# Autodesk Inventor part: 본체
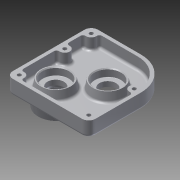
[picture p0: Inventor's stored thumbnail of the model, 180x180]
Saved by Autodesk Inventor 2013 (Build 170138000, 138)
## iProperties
Created: 2015-11
Part Number: 본체
Material: 알루미늄 6061
Document SubType Name: Modeling
Designer: Administrator
Density: 1 g/cm^3
Author: Administrator
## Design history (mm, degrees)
sketch "스케치1"
  geometry: L1 (-44.906, -34.091)-(39.094, -34.091); L2 (47.094, -26.091)-(47.094, 28.909); L3 (7.094, 68.909)-(-44.906, 68.909); L4 (-52.906, 60.909)-(-52.906, -26.091); A1 r 40 centre (7.094, 28.909) between (47.094, 28.909) and (7.094, 68.909); A2 r 8 centre (-44.906, 60.909) between (-44.906, 68.909) and (-52.906, 60.909); A3 r 8 centre (-44.906, -26.091) between (-52.906, -26.091) and (-44.906, -34.091); A4 r 8 centre (39.094, -26.091) between (39.094, -34.091) and (47.094, -26.091); 4 further points
  constraints: 8 end point, 8 point on circle, 8 tangent, 6 point on line, 4 centre point, 2 equal radius, 2 parallel, 1 horizontal, 1 perpendicular
  dimensions: "d0" = 103 distance of point (-52.906, 68.909) point (-52.906, -34.091); "d2" = 100 distance of point (-52.906, -34.091) point (47.094, -34.091); "d3" = 40 radius of A1; "d4" = 8 radius of A2
extrude "돌출1" new body sketch "스케치1" distance "d5" = 18; taper "d6" = 0 deg
sketch "스케치2"
  geometry: L1 (47.094, -26.091)-(47.094, 28.909) reference; L2 (7.094, 68.909)-(-44.906, 68.909) reference; L3 (-52.906, 60.909)-(-52.906, -26.091) reference; L4 (-44.906, -34.091)-(39.094, -34.091) reference; A1 r 40 centre (7.094, 28.909) between (47.094, 28.909) and (7.094, 68.909) reference; A2 r 8 centre (-44.906, 60.909) between (-44.906, 68.909) and (-52.906, 60.909) reference; A3 r 8 centre (-44.906, -26.091) between (-52.906, -26.091) and (-44.906, -34.091) reference; A4 r 8 centre (39.094, -26.091) between (39.094, -34.091) and (47.094, -26.091) reference; 1 further point
feature "쉘1" dims "d9" = 4
sketch "스케치3"
  geometry: L1 (88, 4)-(88, 59) reference; L2 (52, 95)-(0, 95) reference; L3 (-4, 91)-(-4, 4) reference; L4 (0, 0)-(84, 0) reference; L5 (84, -4)-(0, -4) reference; L6 (-8, 4)-(-8, 91) reference; L7 (0, 99)-(52, 99) reference; L8 (92, 59)-(92, 4) reference; L9 (0, 59)-(84, 59); C1 r 6 at (0, 91); C2 r 6 at (0, 4); C3 r 6 at (0, 59); C4 r 6 at (84, 59); C5 r 6 at (84, 4); A1 r 4 centre (0, 91) between (0, 95) and (-4, 91) reference; A2 r 4 centre (0, 4) between (-4, 4) and (0, 0) reference; A3 r 4 centre (84, 4) between (84, 0) and (88, 4) reference; A4 r 36 centre (52, 59) between (88, 59) and (52, 95) reference; A5 r 4 centre (0, 91) between (0, 95) and (-4, 91) reference; A6 r 4 centre (0, 4) between (-4, 4) and (0, 0) reference; A7 r 8 centre (84, 4) between (84, -4) and (92, 4) reference; A8 r 8 centre (0, 4) between (-8, 4) and (0, -4) reference; A9 r 8 centre (0, 91) between (0, 99) and (-8, 91) reference; A10 r 40 centre (52, 59) between (92, 59) and (52, 99) reference; 1 further point
  constraints: 5 centre point, 4 coincident, 2 end point, 1 perpendicular
  dimensions: "d10" = 12 diameter of C1; "d12" = 6 radius of C2; "d14" = 6 radius of C3; "d15" = 84 distance of L9.start L9.end; "d16" = 6 radius of C4; "d17" = 6 radius of C5
extrude "돌출2" join sketch "스케치3" distance "d18" = 14; taper "d19" = 0 deg
fillet "모깎기2" dims "d21" = 3
fillet "모깎기3" dims "d22" = 3
sketch "스케치4"
  geometry: L1 (0, 89)-(43.056, 89) reference; L2 (-9.944, 64.944)-(-9.944, 79.056) reference; L3 (-9.944, 9.944)-(-9.944, 47.056) reference; L4 (66.111, 0)-(0, 0) reference; L5 (76.056, 47.056)-(76.056, 9.944) reference; A1 r 33 centre (43.056, 56) between (74.806, 64.997) and (43.056, 89) reference; A2 r 9 centre (-8.944, 88) between (-9.944, 79.056) and (0, 89) reference; A3 r 9 centre (-8.944, 56) between (-9.944, 47.056) and (-9.944, 64.944) reference; A4 r 9 centre (-8.944, 1) between (0, 0) and (-9.944, 9.944) reference; A5 r 9 centre (75.056, 1) between (76.056, 9.944) and (66.111, 0) reference; A6 r 9 centre (75.056, 56) between (74.806, 64.997) and (76.056, 47.056) reference; 1 further point
sketch "스케치5"
  geometry: L1 (0, 89)-(43.056, 89) reference; L2 (-9.944, 64.944)-(-9.944, 79.056) reference; L3 (-9.944, 9.944)-(-9.944, 47.056) reference; L4 (66.111, 0)-(0, 0) reference; L5 (76.056, 47.056)-(76.056, 9.944) reference; A1 r 33 centre (43.056, 56) between (74.806, 64.997) and (43.056, 89) reference; A2 r 9 centre (-8.944, 88) between (-9.944, 79.056) and (0, 89) reference; A3 r 9 centre (-8.944, 56) between (-9.944, 47.056) and (-9.944, 64.944) reference; A4 r 9 centre (-8.944, 1) between (0, 0) and (-9.944, 9.944) reference; A5 r 9 centre (75.056, 1) between (76.056, 9.944) and (66.111, 0) reference; A6 r 9 centre (75.056, 56) between (74.806, 64.997) and (76.056, 47.056) reference; 1 further point
sketch "스케치6"
  geometry: A1 r 6 centre (-44.906, -26.091) between (-38.943, -26.758) and (-45.573, -20.128) reference; A2 r 6 centre (-44.906, 28.909) between (-45.573, 22.946) and (-45.573, 34.872) reference; A3 r 6 centre (39.094, 28.909) between (38.927, 34.906) and (39.761, 22.946) reference; A4 r 8 centre (-44.906, 60.909) between (-44.906, 68.909) and (-52.906, 60.909) reference; A5 r 8 centre (39.094, -26.091) between (39.094, -34.091) and (47.094, -26.091) reference; 1 further point
hole "구멍1" sketch "스케치6" at (-44.906, 60.909), (-44.906, 28.909), (39.094, 28.909), (39.094, -26.091), (-44.906, -26.091) diameter "d23" = 4.5; stored, may be unused: countersink angle "d27" = 90 deg, drill point angle "d29" = 118 deg; dims "d24" = 6, "d25" = 4, "d26" = 2, "d28" = 8
sketch "스케치7"
  geometry: C1 r 2.25 at (-39.094, -26.091) reference; C2 r 2.25 at (44.906, 28.909) reference; C3 r 2.25 at (44.906, 60.909) reference; C4 r 2.25 at (-39.094, 28.909) reference; C5 r 2.25 at (44.906, -26.091) reference; 1 further point
hole "구멍2" sketch "스케치7" at (-39.094, 28.909), (-39.094, -26.091), (44.906, -26.091), (44.906, 28.909), (44.906, 60.909) diameter "d30" = 4.5; stored, may be unused: countersink angle "d34" = 90 deg, drill point angle "d36" = 118 deg; dims "d31" = 6, "d32" = 8, "d33" = 4.4, "d35" = 17
sketch "스케치8"
  geometry: L1 (-16.944, 88)-(-16.944, 1) reference; L2 (-8.944, -7)-(75.056, -7) reference; L3 (-16.944, 1)-(-16.944, -7); L4 (-9.944, -7)-(-16.944, -7); L5 (-16.944, -7)-(13.056, -7); L6 (13.056, -7)-(13.056, 23); L7 (13.056, 23)-(-16.944, 23); L8 (-16.944, 23)-(-16.944, -7); L9 (-16.944, -7)-(46.056, -7); L10 (46.056, -7)-(46.056, 53); L11 (46.056, 53)-(-16.944, 53); L12 (-16.944, 53)-(-16.944, -7); C1 r 20 at (13.056, 23); C2 r 20 at (46.056, 53); 1 further point
  constraints: 20 end point, 4 parallel, 4 perpendicular, 2 centre point, 2 coincident, 2 horizontal
  dimensions: "d37" = 30 distance of L7.end L6.end; "d38" = 30 distance of L6.end L5.end; "d40" = 20 radius of C1; "d41" = 63 distance of L11.end L10.end; "d42" = 60 distance of L10.end L9.end; "d43" = 20 radius of C2
extrude "돌출3" join sketch "스케치8" distance "d44" = 11; taper "d45" = -10 deg
fillet "모깎기4" dims "d46" = 3
sketch "스케치10"
  geometry: C1 r 18.06 at (0, 0) reference; 1 further point
hole "구멍4" sketch "스케치10" at (0, 0) diameter "d54" = 20; stored, may be unused: countersink angle "d58" = 90 deg, drill point angle "d60" = 118 deg; dims "d55" = 6, "d56" = 32, "d57" = 9, "d59" = 50
chamfer "모따기1" distance "d61" = 1; stored, may be unused: second distance "d62" = 2, angle "d63" = 45 deg
fillet "모깎기5" dims "d64" = 0.3
sketch "스케치11"
  geometry: C1 r 10 at (22.906, -4.091) reference; C2 r 25 at (22.906, -2.936); 1 further point
  constraints: 1 centre point
  dimensions: "d65" = 25 radius of C2
extrude "돌출4" join sketch "스케치11" distance "d66" = 15; taper "d67" = -10 deg
sketch "스케치15"
  geometry: L1 (52.906, -26.091)-(52.906, 60.909) reference; L2 (44.906, 68.909)-(-7.094, 68.909) reference; 2 further points
  constraints: 1 other
  dimensions: "d91" = 40 distance from line of L1 point (12.906, 48.909); "d92" = 20 distance from line of point (12.906, 48.909) L2
feature "엠보싱1" sketch "스케치15" dims "d0" = 103, "d2" = 100, "d3" = 40, "d4" = 8, "d93" = 0.5, "d94" = 0
fillet "모깎기8" dims "d95" = 3
fillet "모깎기9" dims "d96" = 3
sketch "스케치16"
  geometry: C1 r 18.06 at (0, 0) reference; C2 r 16 at (0, 0); 1 further point
  constraints: 1 centre point, 1 coincident
  dimensions: "d97" = 32 diameter of C2
extrude "돌출7" cut sketch "스케치16" distance "d98" = 9; taper "d99" = 0 deg
chamfer "모따기3" distance "d103" = 1; stored, may be unused: second distance "d104" = 2, angle "d105" = 45 deg
fillet "모깎기10" dims "d106" = 0.3
sketch "스케치18"
  geometry: C1 r 12.645 at (0, -1.155) reference; C2 r 14 at (0, -1.155); 1 further point
  constraints: 1 centre point, 1 coincident
  dimensions: "d107" = 28 diameter of C2
extrude "돌출9" cut sketch "스케치18" distance "d108" = 11; taper "d109" = 0 deg
chamfer "모따기4" distance "d110" = 1; stored, may be unused: second distance "d111" = 2, angle "d112" = 45 deg
fillet "모깎기11" dims "d113" = 0.3
sketch "스케치19"
  geometry: C1 r 13.7 at (0, 0) reference; C2 r 12 at (0, 0); 1 further point
  constraints: 1 centre point, 1 coincident
  dimensions: "d114" = 24 diameter of C2
extrude "돌출10" cut sketch "스케치19" distance "d115" = 2; taper "d116" = 0 deg
fillet "모깎기12" dims "d117" = 2
sketch "스케치20"
  geometry: C1 r 10 at (0, 0) reference; C2 r 10 at (0, 0); 1 further point
  constraints: 1 centre point, 1 coincident
  dimensions: "d118" = 20 diameter of C2
extrude "돌출11" cut sketch "스케치20" stored distance "d119" = 2; taper "d120" = 0 deg
node "솔리드1"
node "절단 모서리 투영1"
